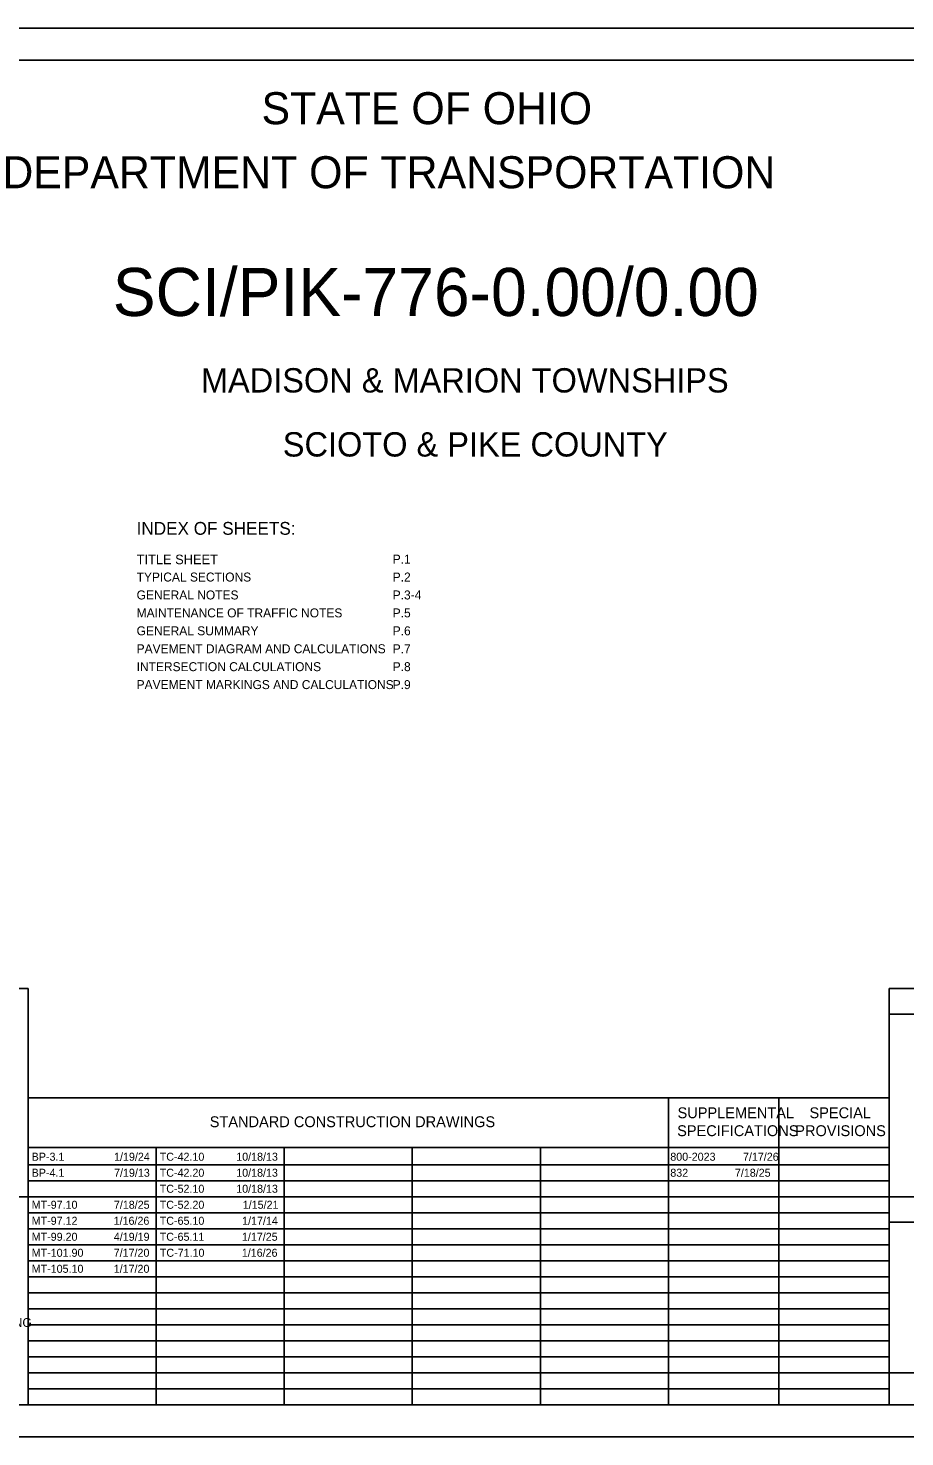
# Model space of a CAD drawing. Extents: x 0 to 40.8, y 0 to 22.
# Drawn here: x 10.15 to 23.84, y 0 to 22 of the extents above; entities that cross this region are included whole.
import ezdxf

# ---------------------------------------------------------------- set-up
doc = ezdxf.new("R2010")
doc.units = 0
for name, color, linetype in [('Default', 7, 'Continuous'), ('SH_Border', 7, 'Continuous'), ('SH_Cut_Line', 7, 'Continuous'), ('SH_Data', 7, 'Continuous'), ('SH_Text', 7, 'Continuous')]:
    doc.layers.add(name, color=color, linetype=linetype)

msp = doc.modelspace()

# ---------------------------------------------------------------- linework, layer by layer
at = {"layer": 'SH_Border'}
msp.add_lwpolyline([(1.5, 21.5), (33.5, 21.5), (33.5, 0.5), (1.5, 0.5)], close=True, dxfattribs=at)
at = {"layer": 'SH_Cut_Line'}
msp.add_lwpolyline([(0, 0), (34, 0), (34, 22), (0, 22)], close=True, dxfattribs=at)
at = {"layer": 'SH_Data'}
for p, q in [((23.6, 6.6), (26.4, 6.6)), ((10.15, 5.292), (23.6, 5.292)), ((10.15, 0.5), (10.15, 5.292)), ((20.15, 0.5), (20.15, 5.292)), ((21.875, 0.5), (21.875, 5.292)), ((23.6, 0.5), (23.6, 5.292)), ((10.15, 4.521), (23.6, 4.521)), ((12.15, 0.5), (12.15, 4.521)), ((14.15, 0.5), (14.15, 4.521)), ((16.15, 0.5), (16.15, 4.521)), ((18.15, 0.5), (18.15, 4.521)), ((10.15, 4.25), (23.6, 4.25)), ((10.15, 4), (23.6, 4)), ((10.15, 3.75), (23.6, 3.75)), ((23.6, 0.5), (23.6, 3.75)), ((23.6, 3.75), (26.4, 3.75)), ((10.15, 3.5), (23.6, 3.5)), ((23.6, 3.35), (26.4, 3.35)), ((23.6, 3.35), (26.4, 3.35)), ((10.15, 3.25), (23.6, 3.25)), ((10.15, 3), (23.6, 3)), ((10.15, 2.75), (23.6, 2.75)), ((10.15, 2.5), (23.6, 2.5)), ((10.15, 2.25), (23.6, 2.25)), ((10.15, 2), (23.6, 2)), ((10.15, 1.75), (23.6, 1.75)), ((10.15, 1.5), (23.6, 1.5)), ((10.15, 1.25), (23.6, 1.25)), ((10.15, 1), (23.6, 1)), ((10.15, 0.75), (23.6, 0.75)), ((23.6, 0.5), (26.4, 0.5))]:
    msp.add_line(p, q, dxfattribs=at)
for points in [[(10.15, 7), (7.35, 7), (7.35, 3.75), (10.15, 3.75)], [(26.4, 7), (23.6, 7), (23.6, 3.75), (26.4, 3.75)], [(10.15, 3.75), (7.35, 3.75), (7.35, 0.5), (10.15, 0.5)], [(26.4, 3.75), (23.6, 3.75), (23.6, 0.5), (26.4, 0.5)], [(23.6, 0.5), (23.6, 1), (26.4, 1), (26.4, 0.5)]]:
    msp.add_lwpolyline(points, close=True, dxfattribs=at)

# ---------------------------------------------------------------- texts
at = {"layer": 'Default'}
for s, p in [('BP-3.1', (10.205, 4.312)), ('1/19/24', (11.492, 4.312)), ('TC-42.10', (12.205, 4.312)), ('10/18/13', (13.4, 4.312)), ('800-2023', (20.18, 4.312)), ('7/17/26', (21.315, 4.312)), ('BP-4.1', (10.205, 4.062)), ('7/19/13', (11.492, 4.062)), ('TC-42.20', (12.205, 4.062)), ('10/18/13', (13.4, 4.062)), ('832', (20.18, 4.062)), ('7/18/25', (21.189, 4.062)), ('TC-52.10', (12.205, 3.812)), ('10/18/13', (13.4, 3.812)), ('MT-97.10', (10.205, 3.562)), ('7/18/25', (11.489, 3.562)), ('TC-52.20', (12.205, 3.562)), ('1/15/21', (13.502, 3.562)), ('MT-97.12', (10.205, 3.312)), ('1/16/26', (11.485, 3.312)), ('TC-65.10', (12.205, 3.312)), ('1/17/14', (13.492, 3.312)), ('MT-99.20', (10.205, 3.062)), ('4/19/19', (11.488, 3.062)), ('TC-65.11', (12.205, 3.062)), ('1/17/25', (13.489, 3.062)), ('MT-101.90', (10.205, 2.812)), ('7/17/20', (11.486, 2.812)), ('TC-71.10', (12.207, 2.812)), ('1/16/26', (13.487, 2.812)), ('MT-105.10', (10.205, 2.562)), ('1/17/20', (11.486, 2.562))]:
    msp.add_text(s, height=0.125, dxfattribs=at).set_placement(p)
at = {"layer": 'SH_Text'}
for s, height, p in [('STATE OF OHIO', 0.5, (13.795, 20.5)), ('DEPARTMENT OF TRANSPORTATION', 0.5, (9.747, 19.5)), ('SCI/PIK-776-0.00/0.00', 0.75, (11.471, 17.505)), ('MADISON & MARION TOWNSHIPS', 0.38, (12.848, 16.31)), ('SCIOTO & PIKE COUNTY', 0.38, (14.127, 15.31)), ('INDEX OF SHEETS:', 0.2, (11.844, 14.088)), ('TITLE SHEET', 0.15, (11.844, 13.628)), ('P.1', 0.14, (15.844, 13.638)), ('TYPICAL SECTIONS', 0.14, (11.844, 13.358)), ('P.2', 0.14, (15.844, 13.358)), ('GENERAL NOTES', 0.14, (11.844, 13.078)), ('P.3-4', 0.14, (15.844, 13.078)), ('MAINTENANCE OF TRAFFIC NOTES', 0.14, (11.844, 12.798)), ('P.5', 0.14, (15.844, 12.798)), ('GENERAL SUMMARY', 0.14, (11.844, 12.518)), ('P.6', 0.14, (15.844, 12.518)), ('PAVEMENT DIAGRAM AND CALCULATIONS', 0.14, (11.844, 12.238)), ('P.7', 0.14, (15.844, 12.238)), ('INTERSECTION CALCULATIONS', 0.14, (11.844, 11.958)), ('P.8', 0.14, (15.844, 11.958)), ('PAVEMENT MARKINGS AND CALCULATIONS', 0.14, (11.844, 11.678)), ('P.9', 0.14, (15.844, 11.678)), ('SUPPLEMENTAL', 0.17, (20.293, 4.976)), ('SPECIAL', 0.17, (22.354, 4.976)), ('STANDARD CONSTRUCTION DRAWINGS', 0.17, (12.986, 4.836)), ('SPECIFICATIONS', 0.17, (20.287, 4.696)), ('PROVISIONS', 0.17, (22.132, 4.696)), ('DISTRICT 9 ENGINEERING', 0.14, (7.824, 1.715))]:
    msp.add_text(s, height=height, dxfattribs=at).set_placement(p)

doc.saveas('drawing.dxf')
